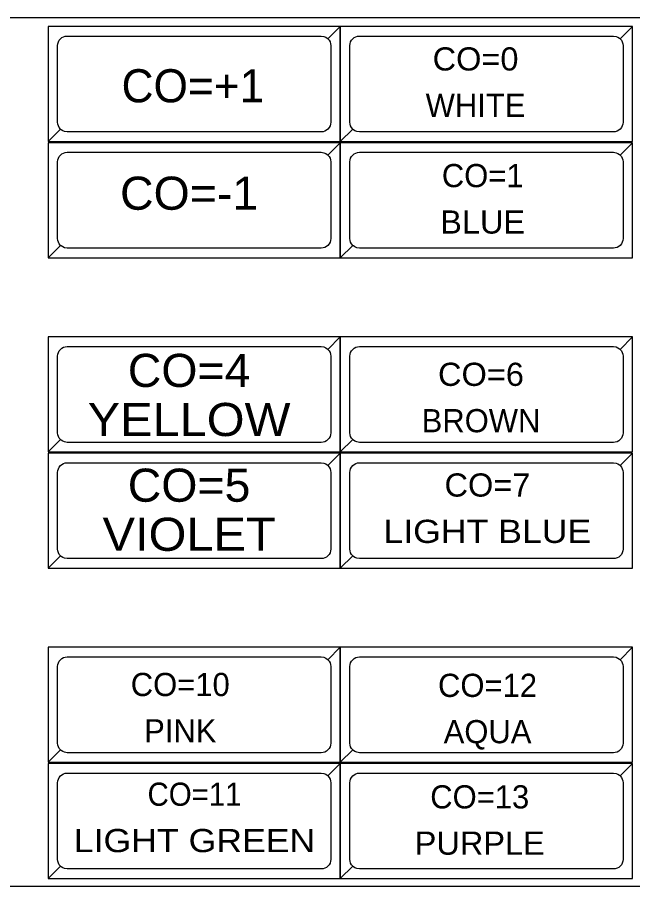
# Model space of a CAD drawing. Extents: x 16898 to 16911.6, y 15837.8 to 15842.
# Drawn here: x 16900.726 to 16902.171, y 15839.972 to 15842.012 of the extents above; entities that cross this region are included whole.
import ezdxf
from ezdxf.enums import TextEntityAlignment as Align

# ---------------------------------------------------------------- set-up
doc = ezdxf.new("R2010")
doc.units = 0
doc.header["$LTSCALE"] = 0.018
for name, color, linetype, lineweight in [('1', 7, 'Continuous', 25), ('2', 7, 'Continuous', 13), ('5', 7, 'Continuous', 13)]:
    doc.layers.add(name, color=color, linetype=linetype, lineweight=lineweight)

msp = doc.modelspace()

# ---------------------------------------------------------------- linework, layer by layer
at = {"layer": '1'}
for points in [[(16897.9955, 15839.9723), (16897.9955, 15842.0124), (16911.4764, 15842.0124), (16911.5674, 15841.9251), (16911.5674, 15840.0599), (16911.4764, 15839.9723)], [(16900.798, 15841.7211), (16901.4844, 15841.7211), (16901.4844, 15841.9911), (16900.798, 15841.9911)], [(16900.798, 15841.7211), (16901.4844, 15841.7211), (16901.4844, 15841.9911), (16901.4553, 15841.962), (16901.4581, 15841.9586), (16901.4602, 15841.9547), (16901.4614, 15841.9505), (16901.4619, 15841.9461), (16901.4619, 15841.7661), (16901.4614, 15841.7617), (16901.4602, 15841.7575), (16901.4581, 15841.7536), (16901.4553, 15841.7502), (16901.4553, 15841.7502), (16901.4519, 15841.7474), (16901.448, 15841.7453), (16901.4438, 15841.744), (16901.4394, 15841.7436), (16900.843, 15841.7436), (16900.8364, 15841.7446), (16900.8324, 15841.7463), (16900.8287, 15841.7487), (16900.8271, 15841.7502)], [(16901.4844, 15841.9911), (16900.798, 15841.9911), (16900.798, 15841.7211), (16900.8271, 15841.7502), (16900.8243, 15841.7536), (16900.8222, 15841.7575), (16900.8209, 15841.7617), (16900.8205, 15841.7661), (16900.8205, 15841.9461), (16900.8209, 15841.9505), (16900.8222, 15841.9547), (16900.8243, 15841.9586), (16900.8271, 15841.962), (16900.8271, 15841.962), (16900.8305, 15841.9648), (16900.8344, 15841.9669), (16900.8386, 15841.9681), (16900.843, 15841.9686), (16901.4394, 15841.9686), (16901.446, 15841.9676), (16901.45, 15841.9659), (16901.4537, 15841.9635), (16901.4553, 15841.962)], [(16901.4844, 15841.7211), (16902.1708, 15841.7211), (16902.1708, 15841.9911), (16901.4844, 15841.9911)], [(16901.4844, 15841.7211), (16902.1708, 15841.7211), (16902.1708, 15841.9911), (16902.1417, 15841.962), (16902.1445, 15841.9586), (16902.1466, 15841.9547), (16902.1478, 15841.9505), (16902.1483, 15841.9461), (16902.1483, 15841.7661), (16902.1478, 15841.7617), (16902.1466, 15841.7575), (16902.1445, 15841.7536), (16902.1417, 15841.7502), (16902.1417, 15841.7502), (16902.1383, 15841.7474), (16902.1344, 15841.7453), (16902.1302, 15841.744), (16902.1258, 15841.7436), (16901.5294, 15841.7436), (16901.5228, 15841.7446), (16901.5188, 15841.7463), (16901.5151, 15841.7487), (16901.5135, 15841.7502)], [(16902.1708, 15841.9911), (16901.4844, 15841.9911), (16901.4844, 15841.7211), (16901.5135, 15841.7502), (16901.5107, 15841.7536), (16901.5086, 15841.7575), (16901.5073, 15841.7617), (16901.5069, 15841.7661), (16901.5069, 15841.9461), (16901.5073, 15841.9505), (16901.5086, 15841.9547), (16901.5107, 15841.9586), (16901.5135, 15841.962), (16901.5135, 15841.962), (16901.5169, 15841.9648), (16901.5208, 15841.9669), (16901.525, 15841.9681), (16901.5294, 15841.9686), (16902.1258, 15841.9686), (16902.1324, 15841.9676), (16902.1364, 15841.9659), (16902.1401, 15841.9635), (16902.1417, 15841.962)], [(16900.798, 15841.4483), (16901.4844, 15841.4483), (16901.4844, 15841.7183), (16900.798, 15841.7183)], [(16900.798, 15841.4483), (16901.4844, 15841.4483), (16901.4844, 15841.7183), (16901.4553, 15841.6892), (16901.4581, 15841.6858), (16901.4602, 15841.6819), (16901.4614, 15841.6777), (16901.4619, 15841.6733), (16901.4619, 15841.4933), (16901.4614, 15841.4889), (16901.4602, 15841.4847), (16901.4581, 15841.4808), (16901.4553, 15841.4774), (16901.4553, 15841.4774), (16901.4519, 15841.4746), (16901.448, 15841.4725), (16901.4438, 15841.4712), (16901.4394, 15841.4708), (16900.843, 15841.4708), (16900.8364, 15841.4718), (16900.8324, 15841.4735), (16900.8287, 15841.4759), (16900.8271, 15841.4774)], [(16901.4844, 15841.7183), (16900.798, 15841.7183), (16900.798, 15841.4483), (16900.8271, 15841.4774), (16900.8243, 15841.4808), (16900.8222, 15841.4847), (16900.8209, 15841.4889), (16900.8205, 15841.4933), (16900.8205, 15841.6733), (16900.8209, 15841.6777), (16900.8222, 15841.6819), (16900.8243, 15841.6858), (16900.8271, 15841.6892), (16900.8271, 15841.6892), (16900.8305, 15841.692), (16900.8344, 15841.6941), (16900.8386, 15841.6953), (16900.843, 15841.6958), (16901.4394, 15841.6958), (16901.446, 15841.6948), (16901.45, 15841.6931), (16901.4537, 15841.6907), (16901.4553, 15841.6892)], [(16901.4844, 15841.4483), (16902.1708, 15841.4483), (16902.1708, 15841.7183), (16901.4844, 15841.7183)], [(16901.4844, 15841.4483), (16902.1708, 15841.4483), (16902.1708, 15841.7183), (16902.1417, 15841.6892), (16902.1445, 15841.6858), (16902.1466, 15841.6819), (16902.1478, 15841.6777), (16902.1483, 15841.6733), (16902.1483, 15841.4933), (16902.1478, 15841.4889), (16902.1466, 15841.4847), (16902.1445, 15841.4808), (16902.1417, 15841.4774), (16902.1417, 15841.4774), (16902.1383, 15841.4746), (16902.1344, 15841.4725), (16902.1302, 15841.4712), (16902.1258, 15841.4708), (16901.5294, 15841.4708), (16901.5228, 15841.4718), (16901.5188, 15841.4735), (16901.5151, 15841.4759), (16901.5135, 15841.4774)], [(16902.1708, 15841.7183), (16901.4844, 15841.7183), (16901.4844, 15841.4483), (16901.5135, 15841.4774), (16901.5107, 15841.4808), (16901.5086, 15841.4847), (16901.5073, 15841.4889), (16901.5069, 15841.4933), (16901.5069, 15841.6733), (16901.5073, 15841.6777), (16901.5086, 15841.6819), (16901.5107, 15841.6858), (16901.5135, 15841.6892), (16901.5135, 15841.6892), (16901.5169, 15841.692), (16901.5208, 15841.6941), (16901.525, 15841.6953), (16901.5294, 15841.6958), (16902.1258, 15841.6958), (16902.1324, 15841.6948), (16902.1364, 15841.6931), (16902.1401, 15841.6907), (16902.1417, 15841.6892)], [(16900.798, 15840.9924), (16901.4844, 15840.9924), (16901.4844, 15841.2624), (16900.798, 15841.2624)], [(16900.798, 15840.9924), (16901.4844, 15840.9924), (16901.4844, 15841.2624), (16901.4553, 15841.2333), (16901.4581, 15841.2299), (16901.4602, 15841.226), (16901.4614, 15841.2218), (16901.4619, 15841.2174), (16901.4619, 15841.0374), (16901.4614, 15841.033), (16901.4602, 15841.0288), (16901.4581, 15841.0249), (16901.4553, 15841.0215), (16901.4553, 15841.0215), (16901.4519, 15841.0187), (16901.448, 15841.0166), (16901.4438, 15841.0153), (16901.4394, 15841.0149), (16900.843, 15841.0149), (16900.8364, 15841.0159), (16900.8324, 15841.0176), (16900.8287, 15841.02), (16900.8271, 15841.0215)], [(16901.4844, 15841.2624), (16900.798, 15841.2624), (16900.798, 15840.9924), (16900.8271, 15841.0215), (16900.8243, 15841.0249), (16900.8222, 15841.0288), (16900.8209, 15841.033), (16900.8205, 15841.0374), (16900.8205, 15841.2174), (16900.8209, 15841.2218), (16900.8222, 15841.226), (16900.8243, 15841.2299), (16900.8271, 15841.2333), (16900.8271, 15841.2333), (16900.8305, 15841.2361), (16900.8344, 15841.2382), (16900.8386, 15841.2394), (16900.843, 15841.2399), (16901.4394, 15841.2399), (16901.446, 15841.2389), (16901.45, 15841.2372), (16901.4537, 15841.2348), (16901.4553, 15841.2333)], [(16901.4844, 15840.9924), (16902.1708, 15840.9924), (16902.1708, 15841.2624), (16901.4844, 15841.2624)], [(16901.4844, 15840.9924), (16902.1708, 15840.9924), (16902.1708, 15841.2624), (16902.1417, 15841.2333), (16902.1445, 15841.2299), (16902.1466, 15841.226), (16902.1478, 15841.2218), (16902.1483, 15841.2174), (16902.1483, 15841.0374), (16902.1478, 15841.033), (16902.1466, 15841.0288), (16902.1445, 15841.0249), (16902.1417, 15841.0215), (16902.1417, 15841.0215), (16902.1383, 15841.0187), (16902.1344, 15841.0166), (16902.1302, 15841.0153), (16902.1258, 15841.0149), (16901.5294, 15841.0149), (16901.5228, 15841.0159), (16901.5188, 15841.0176), (16901.5151, 15841.02), (16901.5135, 15841.0215)], [(16902.1708, 15841.2624), (16901.4844, 15841.2624), (16901.4844, 15840.9924), (16901.5135, 15841.0215), (16901.5107, 15841.0249), (16901.5086, 15841.0288), (16901.5073, 15841.033), (16901.5069, 15841.0374), (16901.5069, 15841.2174), (16901.5073, 15841.2218), (16901.5086, 15841.226), (16901.5107, 15841.2299), (16901.5135, 15841.2333), (16901.5135, 15841.2333), (16901.5169, 15841.2361), (16901.5208, 15841.2382), (16901.525, 15841.2394), (16901.5294, 15841.2399), (16902.1258, 15841.2399), (16902.1324, 15841.2389), (16902.1364, 15841.2372), (16902.1401, 15841.2348), (16902.1417, 15841.2333)], [(16900.798, 15840.7196), (16901.4844, 15840.7196), (16901.4844, 15840.9896), (16900.798, 15840.9896)], [(16900.798, 15840.7196), (16901.4844, 15840.7196), (16901.4844, 15840.9896), (16901.4553, 15840.9605), (16901.4581, 15840.9571), (16901.4602, 15840.9532), (16901.4614, 15840.949), (16901.4619, 15840.9446), (16901.4619, 15840.7646), (16901.4614, 15840.7602), (16901.4602, 15840.756), (16901.4581, 15840.7521), (16901.4553, 15840.7487), (16901.4553, 15840.7487), (16901.4519, 15840.7459), (16901.448, 15840.7438), (16901.4438, 15840.7425), (16901.4394, 15840.7421), (16900.843, 15840.7421), (16900.8364, 15840.7431), (16900.8324, 15840.7448), (16900.8287, 15840.7472), (16900.8271, 15840.7487)], [(16901.4844, 15840.9896), (16900.798, 15840.9896), (16900.798, 15840.7196), (16900.8271, 15840.7487), (16900.8243, 15840.7521), (16900.8222, 15840.756), (16900.8209, 15840.7602), (16900.8205, 15840.7646), (16900.8205, 15840.9446), (16900.8209, 15840.949), (16900.8222, 15840.9532), (16900.8243, 15840.9571), (16900.8271, 15840.9605), (16900.8271, 15840.9605), (16900.8305, 15840.9633), (16900.8344, 15840.9654), (16900.8386, 15840.9666), (16900.843, 15840.9671), (16901.4394, 15840.9671), (16901.446, 15840.9661), (16901.45, 15840.9644), (16901.4537, 15840.962), (16901.4553, 15840.9605)], [(16901.4844, 15840.7196), (16902.1708, 15840.7196), (16902.1708, 15840.9896), (16901.4844, 15840.9896)], [(16901.4844, 15840.7196), (16902.1708, 15840.7196), (16902.1708, 15840.9896), (16902.1417, 15840.9605), (16902.1445, 15840.9571), (16902.1466, 15840.9532), (16902.1478, 15840.949), (16902.1483, 15840.9446), (16902.1483, 15840.7646), (16902.1478, 15840.7602), (16902.1466, 15840.756), (16902.1445, 15840.7521), (16902.1417, 15840.7487), (16902.1417, 15840.7487), (16902.1383, 15840.7459), (16902.1344, 15840.7438), (16902.1302, 15840.7425), (16902.1258, 15840.7421), (16901.5294, 15840.7421), (16901.5228, 15840.7431), (16901.5188, 15840.7448), (16901.5151, 15840.7472), (16901.5135, 15840.7487)], [(16902.1708, 15840.9896), (16901.4844, 15840.9896), (16901.4844, 15840.7196), (16901.5135, 15840.7487), (16901.5107, 15840.7521), (16901.5086, 15840.756), (16901.5073, 15840.7602), (16901.5069, 15840.7646), (16901.5069, 15840.9446), (16901.5073, 15840.949), (16901.5086, 15840.9532), (16901.5107, 15840.9571), (16901.5135, 15840.9605), (16901.5135, 15840.9605), (16901.5169, 15840.9633), (16901.5208, 15840.9654), (16901.525, 15840.9666), (16901.5294, 15840.9671), (16902.1258, 15840.9671), (16902.1324, 15840.9661), (16902.1364, 15840.9644), (16902.1401, 15840.962), (16902.1417, 15840.9605)], [(16900.798, 15840.264), (16901.4844, 15840.264), (16901.4844, 15840.534), (16900.798, 15840.534)], [(16900.798, 15840.264), (16901.4844, 15840.264), (16901.4844, 15840.534), (16901.4553, 15840.5049), (16901.4581, 15840.5015), (16901.4602, 15840.4976), (16901.4614, 15840.4934), (16901.4619, 15840.489), (16901.4619, 15840.309), (16901.4614, 15840.3046), (16901.4602, 15840.3004), (16901.4581, 15840.2965), (16901.4553, 15840.2931), (16901.4553, 15840.2931), (16901.4519, 15840.2903), (16901.448, 15840.2882), (16901.4438, 15840.2869), (16901.4394, 15840.2865), (16900.843, 15840.2865), (16900.8364, 15840.2875), (16900.8324, 15840.2892), (16900.8287, 15840.2916), (16900.8271, 15840.2931)], [(16901.4844, 15840.534), (16900.798, 15840.534), (16900.798, 15840.264), (16900.8271, 15840.2931), (16900.8243, 15840.2965), (16900.8222, 15840.3004), (16900.8209, 15840.3046), (16900.8205, 15840.309), (16900.8205, 15840.489), (16900.8209, 15840.4934), (16900.8222, 15840.4976), (16900.8243, 15840.5015), (16900.8271, 15840.5049), (16900.8271, 15840.5049), (16900.8305, 15840.5077), (16900.8344, 15840.5098), (16900.8386, 15840.511), (16900.843, 15840.5115), (16901.4394, 15840.5115), (16901.446, 15840.5105), (16901.45, 15840.5088), (16901.4537, 15840.5064), (16901.4553, 15840.5049)], [(16901.4844, 15840.264), (16902.1708, 15840.264), (16902.1708, 15840.534), (16901.4844, 15840.534)], [(16901.4844, 15840.264), (16902.1708, 15840.264), (16902.1708, 15840.534), (16902.1417, 15840.5049), (16902.1445, 15840.5015), (16902.1466, 15840.4976), (16902.1478, 15840.4934), (16902.1483, 15840.489), (16902.1483, 15840.309), (16902.1478, 15840.3046), (16902.1466, 15840.3004), (16902.1445, 15840.2965), (16902.1417, 15840.2931), (16902.1417, 15840.2931), (16902.1383, 15840.2903), (16902.1344, 15840.2882), (16902.1302, 15840.2869), (16902.1258, 15840.2865), (16901.5294, 15840.2865), (16901.5228, 15840.2875), (16901.5188, 15840.2892), (16901.5151, 15840.2916), (16901.5135, 15840.2931)], [(16902.1708, 15840.534), (16901.4844, 15840.534), (16901.4844, 15840.264), (16901.5135, 15840.2931), (16901.5107, 15840.2965), (16901.5086, 15840.3004), (16901.5073, 15840.3046), (16901.5069, 15840.309), (16901.5069, 15840.489), (16901.5073, 15840.4934), (16901.5086, 15840.4976), (16901.5107, 15840.5015), (16901.5135, 15840.5049), (16901.5135, 15840.5049), (16901.5169, 15840.5077), (16901.5208, 15840.5098), (16901.525, 15840.511), (16901.5294, 15840.5115), (16902.1258, 15840.5115), (16902.1324, 15840.5105), (16902.1364, 15840.5088), (16902.1401, 15840.5064), (16902.1417, 15840.5049)], [(16900.798, 15839.9912), (16901.4844, 15839.9912), (16901.4844, 15840.2612), (16900.798, 15840.2612)], [(16900.798, 15839.9912), (16901.4844, 15839.9912), (16901.4844, 15840.2612), (16901.4553, 15840.2321), (16901.4581, 15840.2287), (16901.4602, 15840.2248), (16901.4614, 15840.2206), (16901.4619, 15840.2162), (16901.4619, 15840.0362), (16901.4614, 15840.0318), (16901.4602, 15840.0276), (16901.4581, 15840.0237), (16901.4553, 15840.0203), (16901.4553, 15840.0203), (16901.4519, 15840.0175), (16901.448, 15840.0154), (16901.4438, 15840.0141), (16901.4394, 15840.0137), (16900.843, 15840.0137), (16900.8364, 15840.0147), (16900.8324, 15840.0164), (16900.8287, 15840.0188), (16900.8271, 15840.0203)], [(16901.4844, 15840.2612), (16900.798, 15840.2612), (16900.798, 15839.9912), (16900.8271, 15840.0203), (16900.8243, 15840.0237), (16900.8222, 15840.0276), (16900.8209, 15840.0318), (16900.8205, 15840.0362), (16900.8205, 15840.2162), (16900.8209, 15840.2206), (16900.8222, 15840.2248), (16900.8243, 15840.2287), (16900.8271, 15840.2321), (16900.8271, 15840.2321), (16900.8305, 15840.2349), (16900.8344, 15840.237), (16900.8386, 15840.2382), (16900.843, 15840.2387), (16901.4394, 15840.2387), (16901.446, 15840.2377), (16901.45, 15840.236), (16901.4537, 15840.2336), (16901.4553, 15840.2321)], [(16901.4844, 15839.9912), (16902.1708, 15839.9912), (16902.1708, 15840.2612), (16901.4844, 15840.2612)], [(16901.4844, 15839.9912), (16902.1708, 15839.9912), (16902.1708, 15840.2612), (16902.1417, 15840.2321), (16902.1445, 15840.2287), (16902.1466, 15840.2248), (16902.1478, 15840.2206), (16902.1483, 15840.2162), (16902.1483, 15840.0362), (16902.1478, 15840.0318), (16902.1466, 15840.0276), (16902.1445, 15840.0237), (16902.1417, 15840.0203), (16902.1417, 15840.0203), (16902.1383, 15840.0175), (16902.1344, 15840.0154), (16902.1302, 15840.0141), (16902.1258, 15840.0137), (16901.5294, 15840.0137), (16901.5228, 15840.0147), (16901.5188, 15840.0164), (16901.5151, 15840.0188), (16901.5135, 15840.0203)], [(16902.1708, 15840.2612), (16901.4844, 15840.2612), (16901.4844, 15839.9912), (16901.5135, 15840.0203), (16901.5107, 15840.0237), (16901.5086, 15840.0276), (16901.5073, 15840.0318), (16901.5069, 15840.0362), (16901.5069, 15840.2162), (16901.5073, 15840.2206), (16901.5086, 15840.2248), (16901.5107, 15840.2287), (16901.5135, 15840.2321), (16901.5135, 15840.2321), (16901.5169, 15840.2349), (16901.5208, 15840.237), (16901.525, 15840.2382), (16901.5294, 15840.2387), (16902.1258, 15840.2387), (16902.1324, 15840.2377), (16902.1364, 15840.236), (16902.1401, 15840.2336), (16902.1417, 15840.2321)]]:
    msp.add_lwpolyline(points, close=True, dxfattribs=at)
at = {"layer": '2'}
msp.add_lwpolyline([(16897.9955, 15839.9723), (16897.9955, 15842.0124), (16911.4764, 15842.0124), (16911.5674, 15841.9251), (16911.5674, 15840.0599), (16911.4764, 15839.9723)], close=True, dxfattribs=at)

# ---------------------------------------------------------------- texts
at = {"layer": '5'}
for s, height, width, p in [('CO=0', 0.0544, 1.05, (16901.802, 15841.8877)), ('CO=-1', 0.07772, 1.05, (16901.1293, 15841.5609)), ('BLUE', 0.0544, 1.05, (16901.8187, 15841.505)), ('CO=4', 0.0777, 1.05, (16901.1293, 15841.145)), ('CO=6', 0.0544, 1.05, (16901.8147, 15841.1475)), ('YELLOW', 0.0777, 1.1, (16901.1292, 15841.0298)), ('CO=5', 0.0777, 1.05, (16901.1292, 15840.8756)), ('CO=7', 0.0544, 1.05, (16901.8299, 15840.8877)), ('VIOLET', 0.0777, 1.1, (16901.1293, 15840.7604)), ('LIGHT BLUE', 0.0544, 1.15, (16901.8297, 15840.7789)), ('CO=11', 0.0544, 0.95, (16901.1421, 15840.162)), ('LIGHT GREEN', 0.0544, 1.15, (16901.142, 15840.0532)), ('PURPLE', 0.0544, 1.05, (16901.8118, 15840.0471))]:
    msp.add_text(s, height=height, dxfattribs=dict(at, width=width)).set_placement(p, align=Align.CENTER)
for s, height, p in [('CO=+1', 0.07772, (16901.1382, 15841.813)), ('WHITE', 0.0544, (16901.802, 15841.7788)), ('CO=1', 0.0544, (16901.8188, 15841.6139)), ('BROWN', 0.0544, (16901.8148, 15841.0387)), ('CO=10', 0.0544, (16901.1085, 15840.4195)), ('CO=12', 0.0544, (16901.8301, 15840.4175)), ('PINK', 0.0544, (16901.1086, 15840.3108)), ('AQUA', 0.0544, (16901.8302, 15840.3088)), ('CO=13', 0.0544, (16901.8118, 15840.1558))]:
    msp.add_text(s, height=height, dxfattribs=at).set_placement(p, align=Align.CENTER)

doc.saveas('drawing.dxf')
